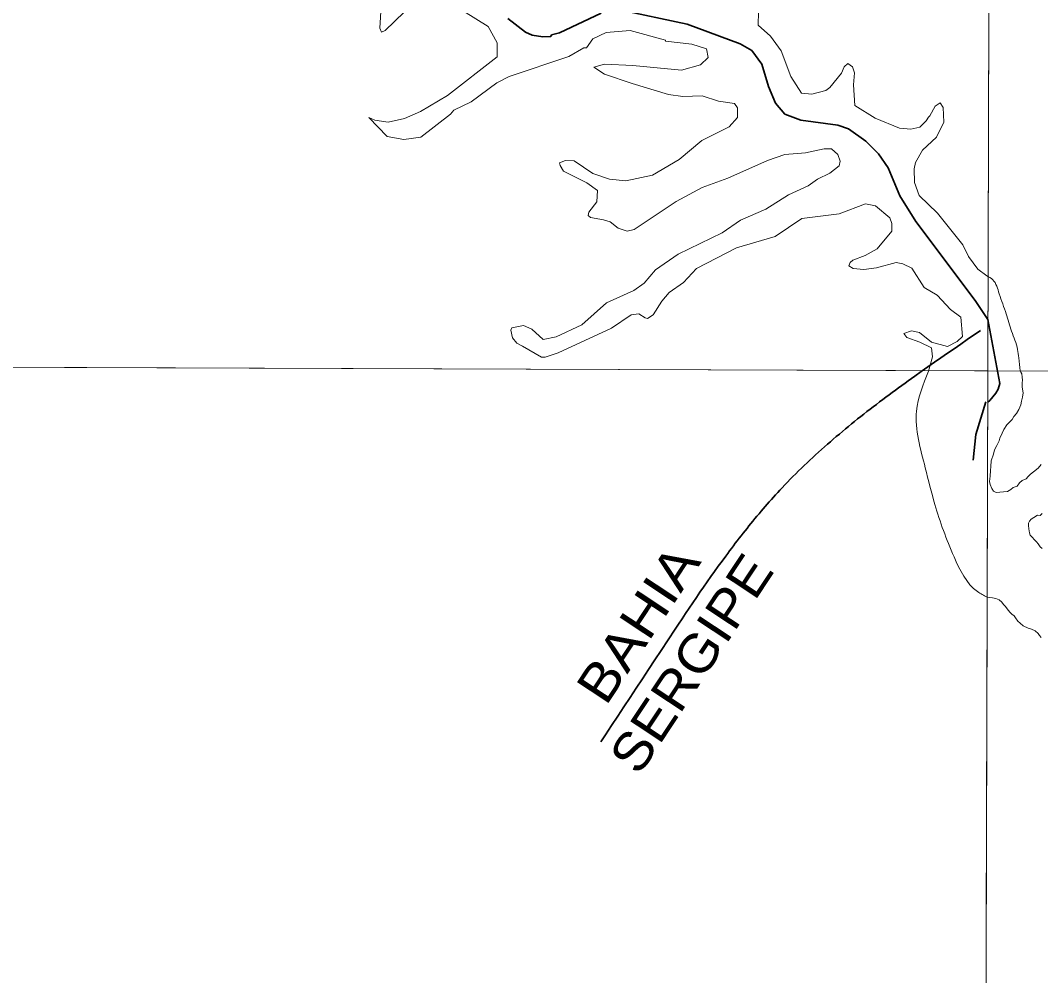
# Model space of a CAD drawing. Extents: x 553962 to 842807, y 8883888 to 9032388.
# Drawn here: x 583564 to 585727, y 8908688 to 8910712 of the extents above; entities that cross this region are included whole.
import ezdxf
from ezdxf.enums import TextEntityAlignment as Align

# ---------------------------------------------------------------- set-up
doc = ezdxf.new("R2010")
doc.units = 0
doc.header["$LTSCALE"] = 200
doc.linetypes.add('LONG_DASH_SHORT_DASH', pattern=[9.9, 6, -1.2, 1.5, -1.2])
doc.layers.add('6', color=7, linetype='Continuous', lineweight=13)

msp = doc.modelspace()

# ---------------------------------------------------------------- linework, layer by layer
at = {"layer": '6'}
msp.add_line((574653.9, 8910009.3), (626625.7, 8909822.1), dxfattribs=at)
for points in [[(585656.3, 8924738.8), (585614.8, 8909969.8), (585573.6, 8896026.7)], [(584328.8, 8910742.2), (584326.1, 8910695.4), (584329.5, 8910687), (584337.2, 8910690.8), (584398.2, 8910749.5)], [(584503.5, 8910731.6), (584555.8, 8910699.3), (584575.1, 8910664.3), (584575, 8910635.1)], [(585613, 8910170.9), (585594.1, 8910185.2), (585574.1, 8910212), (585562.3, 8910236.9), (585508.4, 8910303.8), (585469.5, 8910341.1), (585459.3, 8910368.4), (585458.6, 8910397.8), (585461.4, 8910410.8), (585476.2, 8910437.1), (585506.5, 8910464.7), (585521.5, 8910496.5), (585520.3, 8910527.4), (585514.3, 8910537.5), (585503.6, 8910530.2), (585491.9, 8910510), (585489.3, 8910507.2), (585484.3, 8910499.4), (585470.6, 8910485.7), (585452.1, 8910481.5), (585427.8, 8910483.5), (585376, 8910505.3), (585332.8, 8910531.9), (585330.2, 8910575.4), (585332.3, 8910601), (585328.2, 8910613.7), (585318.2, 8910620.8), (585310.2, 8910614), (585304.7, 8910600.1), (585280.3, 8910570.1), (585271.3, 8910563.7), (585242, 8910556.1), (585220.2, 8910558.3), (585197.6, 8910593.2), (585177.1, 8910647.8), (585154, 8910678.9), (585128, 8910701.8), (585129, 8910730.6)], [(584575, 8910635.1), (584469.8, 8910553.2), (584412.1, 8910519.2), (584378.1, 8910504.3), (584343.7, 8910496.8), (584315.6, 8910501), (584302.5, 8910506.7), (584341.7, 8910466.1), (584377, 8910460), (584413.4, 8910464.9), (584476.2, 8910513.3), (584483.2, 8910521.7), (584519.5, 8910539.6), (584574.1, 8910579.6), (584600.3, 8910593.5), (584727.1, 8910635.6), (584758.7, 8910654.2), (584764.1, 8910654.1), (584777.8, 8910672.8), (584805.8, 8910686.5), (584857.1, 8910690.5), (584931.6, 8910670.4), (584931.7, 8910668.3), (584987.4, 8910661.7), (585018.3, 8910652.2), (585022.5, 8910633.9), (585006, 8910617.9), (584965.8, 8910606.8), (584862.5, 8910616.7)], [(584862.5, 8910616.7), (584802.7, 8910619.4), (584779.5, 8910612.9), (584802.7, 8910598.3), (584861, 8910578.3), (584938.2, 8910555.3), (584968.8, 8910550.7), (585009.7, 8910552), (585044.2, 8910540.8), (585078.1, 8910536.3), (585084.6, 8910527), (585084.6, 8910506.7), (585066.6, 8910486.9), (585008.8, 8910457.8), (584961, 8910417.7), (584904.5, 8910384.2), (584847.7, 8910372.4), (584813.3, 8910375.5), (584777.6, 8910387.8), (584738.3, 8910414.6), (584719.6, 8910415), (584707.3, 8910410.1), (584708.3, 8910404.7), (584715.3, 8910392.9), (584764.8, 8910368.3), (584787.4, 8910351.4), (584785.9, 8910327.6), (584769.2, 8910305.8), (584767.6, 8910298.8), (584772.9, 8910294.4), (584800, 8910289.5), (584814.7, 8910285.1), (584831.6, 8910271.7), (584850.3, 8910265.6), (584865.5, 8910269.3), (584954.5, 8910328.5), (585009.6, 8910357.9), (585064.1, 8910377.6), (585147.9, 8910415.2), (585184.6, 8910428.3), (585228.5, 8910431.7), (585267.9, 8910439.7), (585283.9, 8910439.8), (585297.3, 8910428.1), (585301.8, 8910413.6), (585299.8, 8910404), (585279.9, 8910388.4), (585254.1, 8910375.6), (585234.4, 8910361.7), (585192.5, 8910342.6), (585144.1, 8910312.1), (585090.8, 8910289), (585052.1, 8910261.8), (584958.3, 8910216.9), (584910.5, 8910183.5), (584886.5, 8910155.6), (584864.3, 8910139.8), (584806.9, 8910113.4), (584754.7, 8910067.2), (584700, 8910041.6), (584672.2, 8910035.9), (584648.3, 8910057.9), (584630.4, 8910065.7), (584605.9, 8910061), (584603.9, 8910056.1)], [(584603.9, 8910056.1), (584607.2, 8910039.8), (584616.9, 8910028.5), (584628.5, 8910021.9), (584668.8, 8909998.9), (584676.7, 8909998.9), (584704, 8910007.6), (584817.2, 8910060.3), (584858.8, 8910088.5), (584875.1, 8910090.6), (584888.6, 8910081.7), (584893.5, 8910080.6), (584905.8, 8910088), (584923.7, 8910117.4), (584939.2, 8910135.5), (584969.7, 8910156.6), (584997.7, 8910186.3), (585082.5, 8910230.4), (585164.2, 8910254), (585220.6, 8910292.1), (585299.9, 8910302.5), (585355.9, 8910323.7), (585377.1, 8910318.9), (585407.1, 8910293.7), (585411.8, 8910281.8), (585411.3, 8910265.8), (585380.1, 8910228.3), (585354.8, 8910214.1), (585328.7, 8910204.3), (585323, 8910199), (585320.6, 8910192.2), (585329.2, 8910186.2), (585351.9, 8910184.5), (585378.8, 8910187.8), (585420.4, 8910199.1), (585435, 8910196.4)], [(585435, 8910196.4), (585454.1, 8910186.9), (585480.4, 8910146.2), (585507.6, 8910130.2), (585536, 8910099.4), (585557.7, 8910083.3), (585561.6, 8910042.2), (585550.1, 8910031.9), (585529.2, 8910021.5), (585495.8, 8910030.1), (585470.4, 8910050.8), (585453.4, 8910054.2), (585436.7, 8910048.7), (585443.6, 8910040.4), (585470.9, 8910030.2), (585495.8, 8910018), (585497.8, 8909999), (585489.3, 8909969)], [(585620.4, 8909758.5), (585621.7, 8909767), (585622.4, 8909778.7), (585626.9, 8909793), (585629.5, 8909802.2), (585634.1, 8909811.3), (585639.3, 8909821), (585640.6, 8909826.9), (585645.2, 8909837.3), (585649.1, 8909845.1), (585655.6, 8909854.9), (585662.1, 8909862.1), (585666.7, 8909866.6), (585669.9, 8909872.5), (585675.8, 8909879), (585681, 8909887.4), (585684.9, 8909897.8), (585686.2, 8909905), (585688.8, 8909914.1), (585690.1, 8909923.2), (585688, 8909935.1), (585688.1, 8909940.1), (585688.1, 8909944.1), (585688.2, 8909950.1), (585687.7, 8909956.1), (585686.8, 8909963.1), (585685.3, 8909967.1), (585683.7, 8909969.3)], [(585727.9, 8909770.9), (585721.4, 8909763.7), (585721.4, 8909763.7), (585711.6, 8909755.9), (585705.8, 8909750.7), (585705.8, 8909750.7), (585700.5, 8909745.5), (585696.6, 8909740.9), (585687.5, 8909737), (585682.3, 8909732.5), (585677.1, 8909725.3), (585668.6, 8909722.7), (585664.1, 8909718.2), (585656.9, 8909714.2), (585648.4, 8909712.9), (585640.3, 8909712.6), (585632.8, 8909711.7), (585632.8, 8909711.7), (585626.9, 8909714.9), (585623.7, 8909720.1), (585623.7, 8909720.1), (585619.8, 8909728.6), (585618.5, 8909735.1), (585619.8, 8909746.2), (585620.4, 8909758.5)], [(585730.3, 8909592.8), (585725.8, 8909596.9), (585721.9, 8909602.9), (585718.4, 8909606.9), (585714.9, 8909610.9), (585708.5, 8909617.5), (585704.5, 8909621.5), (585703, 8909626.6), (585701.6, 8909634.6), (585701.2, 8909642.1), (585701.2, 8909646.6), (585703.2, 8909651.1), (585706.8, 8909655.6), (585712.8, 8909659), (585720.3, 8909663.5), (585725.8, 8909663.4), (585730.4, 8909667.4)], [(585613.4, 8909490.1), (585625.1, 8909488.8), (585632, 8909487.3), (585638.9, 8909484.6), (585645, 8909479.2), (585648.1, 8909474.3), (585652.7, 8909470.4), (585655.8, 8909465.1), (585655.8, 8909465.1), (585661.5, 8909458.2), (585661.5, 8909458.2), (585665.7, 8909454.3), (585670.5, 8909450.3), (585674, 8909446.2), (585678.4, 8909439.2), (585683.4, 8909434.7), (585690.2, 8909429.4), (585690.2, 8909429.4), (585700.8, 8909424.5), (585707.3, 8909422), (585715.3, 8909418.4), (585721.7, 8909412.9), (585724.7, 8909408.8), (585728.2, 8909404.8)]]:
    msp.add_lwpolyline(points, dxfattribs=at)
for points in [[(585645.8, 8921027.3), (574684.9, 8921064.7), (574653.9, 8910009.3), (585614.8, 8909969.8)], [(596575.8, 8909932.4), (585614.8, 8909969.8), (585583.8, 8898914.4), (596544.8, 8898874.9)]]:
    msp.add_lwpolyline(points, close=True, dxfattribs=at)
at = {"layer": '6', "linetype": 'LONG_DASH_SHORT_DASH', "lineweight": 35}
for points in [[(584831.7, 8910735), (584977.8, 8910704.3), (585090.2, 8910662.8), (585114.4, 8910648.6), (585135.7, 8910619.1), (585149.9, 8910572.1), (585164.6, 8910536.6), (585184.9, 8910513.7), (585218.4, 8910500.7), (585296.9, 8910489.9), (585319.4, 8910482.1), (585356.6, 8910456.1), (585383.4, 8910429.4), (585403.7, 8910399.5), (585428.8, 8910340.2), (585462.1, 8910286.2), (585588.3, 8910118.5), (585615.1, 8910078.7)], [(584597.3, 8910716), (584635, 8910687.1), (584649.2, 8910681), (584671.7, 8910677.1), (584688.5, 8910678.4), (584689.9, 8910681.4), (584707.2, 8910685.8), (584795.4, 8910727.2)], [(585615.1, 8910078.7), (585640.3, 8909942.8), (585637.2, 8909930.8), (585631.7, 8909922.3), (585625.6, 8909914.8), (585619, 8909906.4), (585614.6, 8909902.8)], [(585583.7, 8909780.1), (585589.5, 8909834.4), (585611.1, 8909903.9)]]:
    msp.add_lwpolyline(points, dxfattribs=at)
at = {"layer": '6'}
for points in [[(585683.7, 8909969.3), (585680.5, 8909997.4), (585678.2, 8910014.6), (585665.5, 8910053.6), (585654.1, 8910090.4), (585639.2, 8910132.8), (585625.4, 8910162.7), (585613, 8910170.9)], [(585489.3, 8909969), (585463.9, 8909884.3), (585482.4, 8909764.2), (585502.7, 8909686.5), (585543.4, 8909575.6), (585593.3, 8909501.7), (585613.4, 8909490.1)]]:
    msp.add_spline(points, degree=3, dxfattribs=at)
at = {"layer": '6', "linetype": 'LONG_DASH_SHORT_DASH', "lineweight": 35}
msp.add_spline([(585599.5, 8910054.8), (585178.8, 8909721.7), (584922.2, 8909376.8), (584712.9, 8909059.8)], degree=3, dxfattribs=at)

# ---------------------------------------------------------------- texts
at = {"layer": '6'}
for s, width, p in [('BAHIA', 1.15, (584907.2, 8909411.3)), ('SERGIPE', 1.1, (585019.6, 8909327.4))]:
    msp.add_text(s, height=80, rotation=56.48, dxfattribs=dict(at, width=width)).set_placement(p, align=Align.CENTER)

doc.saveas('drawing.dxf')
